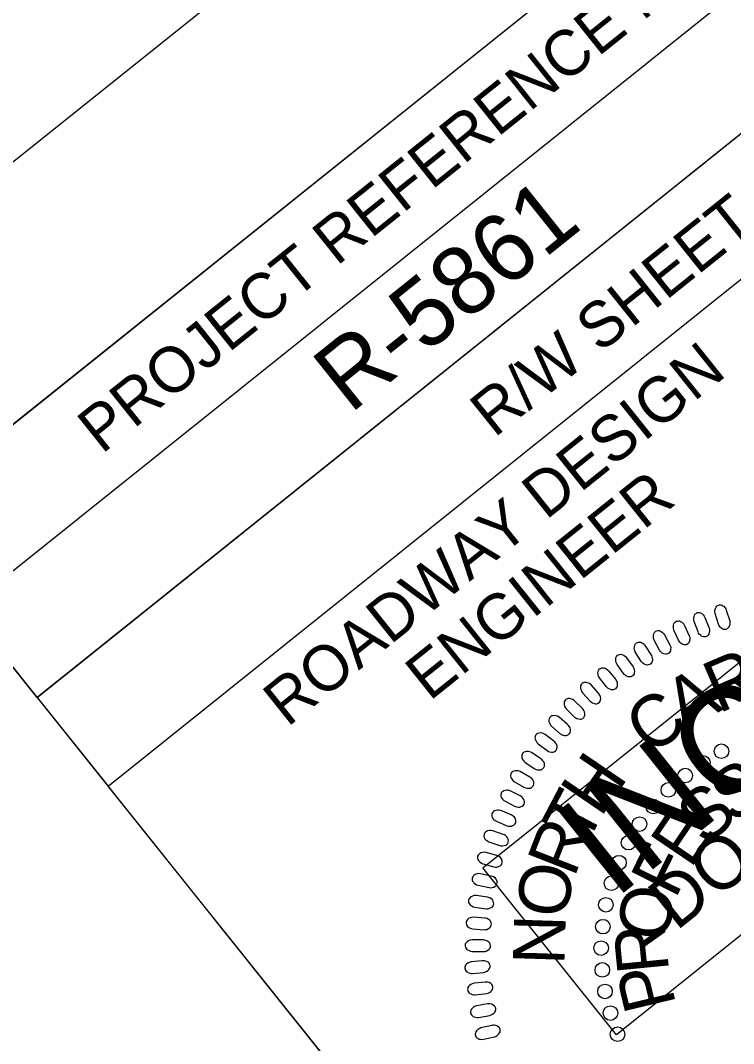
# Model space of a CAD drawing. Extents: x 473546 to 475544, y 505920 to 507827.
# Drawn here: x 474718.5 to 474796.9, y 507616 to 507728.4 of the extents above; entities that cross this region are included whole.
import ezdxf

# ---------------------------------------------------------------- set-up
doc = ezdxf.new("R2010")
doc.units = 0
for name, color, linetype in [('Sheet Clip Boundary CELL', 7, 'Continuous'), ('Sheet Data Field CELL', 7, 'Continuous'), ('Sheet Plan CELL', 7, 'Continuous'), ('Sheet Plot Border Outside CELL', 7, 'Continuous'), ('Sheet Profile Grid Minor CELL', 7, 'Continuous'), ('Sheet Sticker Incomplete CELL', 7, 'Continuous')]:
    doc.layers.add(name, color=color, linetype=linetype)

msp = doc.modelspace()

# ---------------------------------------------------------------- linework, layer by layer
at = {"layer": 'Sheet Clip Boundary CELL'}
msp.add_lwpolyline([(474813.14, 507538.12), (474704.64, 507673.67), (473746.99, 506907.14), (474401.7, 506086.25), (475384.17, 506871.79), (475333.84, 506934.75), (475466.73, 507041), (474969.31, 507663.12)], close=True, dxfattribs=at)
at = {"layer": 'Sheet Plan CELL'}
for p, q in [((474712.51, 507663.81), (474868.71, 507788.81)), ((474720.35, 507654.03), (474876.52, 507779.05)), ((474720.35, 507654.03), (474876.52, 507779.05)), ((474720.35, 507654.03), (474728.16, 507644.28))]:
    msp.add_line(p, q, dxfattribs=at)
for points in [[(474860.89, 507798.63), (473689.75, 506861.33), (474345.84, 506041.55), (475516.97, 506978.83)], [(474704.68, 507673.62), (474860.89, 507798.63), (474876.52, 507779.05), (474720.35, 507654.03)], [(474728.16, 507644.28), (474806.27, 507706.8), (474876.57, 507618.96), (474798.45, 507556.47)]]:
    msp.add_lwpolyline(points, close=True, dxfattribs=at)
at = {"layer": 'Sheet Plot Border Outside CELL'}
msp.add_lwpolyline([(474229.92, 505919.94), (475544.31, 506971.88), (474860.1, 507826.79), (473545.71, 506774.86)], close=True, dxfattribs=at)
at = {"layer": 'Sheet Profile Grid Minor CELL'}
for points in [[(474795.23, 507662.07), (474794.87, 507663.25), (474794.84, 507663.47), (474794.85, 507663.62), (474794.91, 507663.81), (474794.97, 507663.94), (474795.06, 507664.05), (474795.14, 507664.12), (474795.24, 507664.17), (474795.36, 507664.19), (474795.48, 507664.19), (474795.6, 507664.17), (474795.73, 507664.1), (474795.81, 507664.04), (474795.92, 507663.92), (474796.03, 507663.77), (474796.1, 507663.62), (474796.47, 507662.42), (474796.5, 507662.25), (474796.5, 507662.11), (474796.46, 507661.93), (474796.39, 507661.76), (474796.32, 507661.66), (474796.19, 507661.55), (474796.05, 507661.49), (474795.9, 507661.49), (474795.78, 507661.5), (474795.63, 507661.56), (474795.47, 507661.69), (474795.35, 507661.84), (474795.29, 507661.95)], [(474792.99, 507661.22), (474792.56, 507662.37), (474792.52, 507662.59), (474792.52, 507662.74), (474792.56, 507662.93), (474792.61, 507663.07), (474792.69, 507663.19), (474792.77, 507663.26), (474792.87, 507663.32), (474792.98, 507663.34), (474793.11, 507663.35), (474793.23, 507663.33), (474793.36, 507663.28), (474793.44, 507663.22), (474793.56, 507663.11), (474793.68, 507662.96), (474793.75, 507662.82), (474794.2, 507661.65), (474794.24, 507661.48), (474794.25, 507661.33), (474794.22, 507661.15), (474794.17, 507660.98), (474794.1, 507660.87), (474793.98, 507660.76), (474793.85, 507660.69), (474793.69, 507660.67), (474793.58, 507660.68), (474793.42, 507660.73), (474793.25, 507660.85), (474793.12, 507660.99), (474793.05, 507661.1)], [(474790.85, 507660.3), (474790.34, 507661.42), (474790.29, 507661.63), (474790.28, 507661.78), (474790.31, 507661.98), (474790.35, 507662.12), (474790.42, 507662.24), (474790.5, 507662.32), (474790.59, 507662.39), (474790.7, 507662.41), (474790.83, 507662.44), (474790.95, 507662.42), (474791.08, 507662.38), (474791.17, 507662.33), (474791.29, 507662.22), (474791.42, 507662.08), (474791.51, 507661.94), (474792.03, 507660.8), (474792.08, 507660.64), (474792.09, 507660.49), (474792.08, 507660.31), (474792.03, 507660.14), (474791.98, 507660.02), (474791.86, 507659.9), (474791.73, 507659.82), (474791.58, 507659.8), (474791.46, 507659.8), (474791.31, 507659.84), (474791.13, 507659.95), (474790.99, 507660.08), (474790.91, 507660.19)], [(474788.75, 507659.23), (474788.18, 507660.31), (474788.11, 507660.53), (474788.09, 507660.67), (474788.11, 507660.88), (474788.14, 507661.02), (474788.2, 507661.14), (474788.28, 507661.23), (474788.37, 507661.3), (474788.48, 507661.33), (474788.6, 507661.36), (474788.72, 507661.36), (474788.86, 507661.32), (474788.95, 507661.27), (474789.08, 507661.17), (474789.21, 507661.04), (474789.31, 507660.91), (474789.9, 507659.8), (474789.96, 507659.64), (474789.99, 507659.5), (474789.98, 507659.32), (474789.95, 507659.14), (474789.9, 507659.02), (474789.79, 507658.9), (474789.66, 507658.81), (474789.51, 507658.78), (474789.4, 507658.77), (474789.24, 507658.8), (474789.05, 507658.89), (474788.91, 507659.02), (474788.82, 507659.12)], [(474786.74, 507657.99), (474786.1, 507659.04), (474786.02, 507659.25), (474785.99, 507659.39), (474786, 507659.59), (474786.03, 507659.74), (474786.08, 507659.87), (474786.15, 507659.95), (474786.23, 507660.03), (474786.34, 507660.07), (474786.46, 507660.11), (474786.58, 507660.11), (474786.72, 507660.08), (474786.81, 507660.04), (474786.95, 507659.95), (474787.09, 507659.83), (474787.19, 507659.71), (474787.86, 507658.64), (474787.93, 507658.48), (474787.96, 507658.34), (474787.97, 507658.16), (474787.94, 507657.98), (474787.9, 507657.86), (474787.8, 507657.73), (474787.68, 507657.63), (474787.53, 507657.59), (474787.42, 507657.57), (474787.26, 507657.59), (474787.07, 507657.68), (474786.92, 507657.79), (474786.82, 507657.89)], [(474784.79, 507656.65), (474784.09, 507657.66), (474783.99, 507657.86), (474783.95, 507658), (474783.95, 507658.21), (474783.96, 507658.35), (474784.01, 507658.48), (474784.07, 507658.57), (474784.15, 507658.65), (474784.26, 507658.7), (474784.37, 507658.75), (474784.49, 507658.76), (474784.63, 507658.74), (474784.73, 507658.7), (474784.87, 507658.62), (474785.02, 507658.51), (474785.13, 507658.39), (474785.86, 507657.37), (474785.94, 507657.21), (474785.98, 507657.07), (474786, 507656.89), (474785.99, 507656.71), (474785.96, 507656.59), (474785.86, 507656.45), (474785.75, 507656.35), (474785.6, 507656.3), (474785.49, 507656.28), (474785.33, 507656.29), (474785.13, 507656.36), (474784.98, 507656.47), (474784.88, 507656.56)], [(474782.93, 507655.2), (474782.17, 507656.16), (474782.06, 507656.35), (474782.01, 507656.49), (474781.99, 507656.7), (474782, 507656.84), (474782.04, 507656.97), (474782.09, 507657.07), (474782.17, 507657.16), (474782.27, 507657.21), (474782.38, 507657.26), (474782.5, 507657.28), (474782.65, 507657.27), (474782.74, 507657.24), (474782.89, 507657.17), (474783.05, 507657.07), (474783.16, 507656.96), (474783.95, 507655.98), (474784.04, 507655.83), (474784.1, 507655.7), (474784.12, 507655.51), (474784.12, 507655.34), (474784.1, 507655.21), (474784.01, 507655.07), (474783.91, 507654.96), (474783.77, 507654.9), (474783.65, 507654.87), (474783.49, 507654.87), (474783.29, 507654.93), (474783.13, 507655.02), (474783.02, 507655.11)], [(474782.07, 507654.49), (474781.24, 507655.4), (474781.07, 507655.54), (474780.93, 507655.61), (474780.74, 507655.66), (474780.59, 507655.67), (474780.45, 507655.66), (474780.35, 507655.62), (474780.25, 507655.56), (474780.18, 507655.47), (474780.12, 507655.36), (474780.08, 507655.25), (474780.07, 507655.1), (474780.08, 507655.01), (474780.13, 507654.85), (474780.2, 507654.68), (474780.3, 507654.54), (474781.14, 507653.61), (474781.27, 507653.5), (474781.39, 507653.42), (474781.57, 507653.37), (474781.74, 507653.34), (474781.87, 507653.34), (474782.03, 507653.41), (474782.15, 507653.49), (474782.23, 507653.62), (474782.28, 507653.73), (474782.3, 507653.89), (474782.28, 507654.09), (474782.21, 507654.27), (474782.14, 507654.39)], [(474780.29, 507652.81), (474779.41, 507653.67), (474779.23, 507653.79), (474779.09, 507653.85), (474778.89, 507653.89), (474778.74, 507653.9), (474778.61, 507653.87), (474778.51, 507653.83), (474778.41, 507653.76), (474778.35, 507653.66), (474778.29, 507653.56), (474778.26, 507653.44), (474778.26, 507653.3), (474778.27, 507653.2), (474778.33, 507653.05), (474778.42, 507652.88), (474778.52, 507652.75), (474779.42, 507651.87), (474779.55, 507651.77), (474779.68, 507651.7), (474779.86, 507651.66), (474780.04, 507651.64), (474780.16, 507651.65), (474780.32, 507651.72), (474780.44, 507651.82), (474780.51, 507651.95), (474780.55, 507652.06), (474780.56, 507652.22), (474780.53, 507652.43), (474780.44, 507652.6), (474780.37, 507652.71)], [(474778.66, 507651.04), (474777.73, 507651.84), (474777.54, 507651.95), (474777.4, 507652), (474777.2, 507652.03), (474777.05, 507652.02), (474776.92, 507651.99), (474776.82, 507651.94), (474776.73, 507651.86), (474776.67, 507651.77), (474776.62, 507651.66), (474776.59, 507651.54), (474776.6, 507651.39), (474776.62, 507651.3), (474776.69, 507651.15), (474776.79, 507650.99), (474776.9, 507650.86), (474777.85, 507650.04), (474777.99, 507649.95), (474778.13, 507649.89), (474778.31, 507649.86), (474778.48, 507649.85), (474778.61, 507649.87), (474778.76, 507649.95), (474778.87, 507650.05), (474778.94, 507650.19), (474778.97, 507650.31), (474778.97, 507650.47), (474778.92, 507650.67), (474778.83, 507650.84), (474778.75, 507650.94)], [(474777.16, 507649.23), (474776.18, 507649.97), (474775.98, 507650.07), (474775.83, 507650.11), (474775.63, 507650.12), (474775.49, 507650.11), (474775.35, 507650.07), (474775.26, 507650.01), (474775.18, 507649.93), (474775.12, 507649.83), (474775.08, 507649.72), (474775.06, 507649.6), (474775.08, 507649.45), (474775.11, 507649.36), (474775.19, 507649.21), (474775.29, 507649.06), (474775.41, 507648.94), (474776.41, 507648.18), (474776.56, 507648.1), (474776.69, 507648.05), (474776.88, 507648.03), (474777.05, 507648.03), (474777.18, 507648.06), (474777.32, 507648.15), (474777.42, 507648.26), (474777.48, 507648.4), (474777.51, 507648.52), (474777.5, 507648.68), (474777.44, 507648.88), (474777.34, 507649.04), (474777.25, 507649.14)], [(474775.72, 507647.29), (474774.7, 507647.96), (474774.49, 507648.05), (474774.35, 507648.08), (474774.14, 507648.08), (474774, 507648.06), (474773.87, 507648.01), (474773.78, 507647.95), (474773.7, 507647.86), (474773.66, 507647.76), (474773.62, 507647.64), (474773.61, 507647.52), (474773.63, 507647.38), (474773.67, 507647.29), (474773.76, 507647.15), (474773.87, 507647), (474773.99, 507646.89), (474775.04, 507646.2), (474775.19, 507646.12), (474775.33, 507646.08), (474775.52, 507646.07), (474775.7, 507646.09), (474775.82, 507646.12), (474775.95, 507646.22), (474776.05, 507646.34), (474776.1, 507646.48), (474776.12, 507646.6), (474776.1, 507646.76), (474776.03, 507646.95), (474775.91, 507647.11), (474775.82, 507647.2)], [(474774.51, 507645.27), (474773.45, 507645.88), (474773.24, 507645.96), (474773.09, 507645.98), (474772.89, 507645.97), (474772.75, 507645.94), (474772.62, 507645.88), (474772.53, 507645.81), (474772.46, 507645.72), (474772.42, 507645.62), (474772.39, 507645.5), (474772.39, 507645.38), (474772.42, 507645.24), (474772.46, 507645.14), (474772.56, 507645.01), (474772.69, 507644.87), (474772.81, 507644.77), (474773.9, 507644.14), (474774.06, 507644.08), (474774.2, 507644.05), (474774.39, 507644.05), (474774.56, 507644.07), (474774.68, 507644.12), (474774.81, 507644.23), (474774.9, 507644.35), (474774.94, 507644.5), (474774.95, 507644.61), (474774.93, 507644.77), (474774.84, 507644.96), (474774.72, 507645.11), (474774.62, 507645.2)], [(474773.44, 507643.22), (474772.34, 507643.76), (474772.13, 507643.83), (474771.98, 507643.84), (474771.78, 507643.82), (474771.64, 507643.78), (474771.52, 507643.71), (474771.43, 507643.63), (474771.37, 507643.54), (474771.34, 507643.43), (474771.31, 507643.31), (474771.32, 507643.19), (474771.36, 507643.05), (474771.41, 507642.97), (474771.51, 507642.84), (474771.65, 507642.71), (474771.78, 507642.62), (474772.9, 507642.06), (474773.07, 507642), (474773.21, 507641.98), (474773.39, 507641.99), (474773.57, 507642.03), (474773.68, 507642.08), (474773.81, 507642.2), (474773.89, 507642.32), (474773.92, 507642.47), (474773.92, 507642.59), (474773.89, 507642.75), (474773.79, 507642.93), (474773.66, 507643.07), (474773.55, 507643.15)], [(474772.45, 507641.13), (474771.32, 507641.6), (474771.1, 507641.65), (474770.95, 507641.65), (474770.75, 507641.62), (474770.61, 507641.57), (474770.5, 507641.5), (474770.42, 507641.41), (474770.36, 507641.32), (474770.33, 507641.21), (474770.31, 507641.08), (474770.33, 507640.97), (474770.38, 507640.83), (474770.43, 507640.74), (474770.55, 507640.62), (474770.69, 507640.5), (474770.83, 507640.42), (474771.99, 507639.93), (474772.15, 507639.89), (474772.3, 507639.87), (474772.48, 507639.9), (474772.65, 507639.95), (474772.76, 507640), (474772.88, 507640.13), (474772.95, 507640.26), (474772.97, 507640.41), (474772.97, 507640.53), (474772.92, 507640.68), (474772.81, 507640.86), (474772.67, 507640.99), (474772.56, 507641.07)], [(474771.59, 507638.98), (474770.43, 507639.37), (474770.21, 507639.41), (474770.06, 507639.41), (474769.86, 507639.36), (474769.73, 507639.3), (474769.62, 507639.22), (474769.54, 507639.13), (474769.49, 507639.03), (474769.47, 507638.92), (474769.46, 507638.8), (474769.48, 507638.68), (474769.54, 507638.55), (474769.6, 507638.47), (474769.72, 507638.35), (474769.87, 507638.24), (474770.01, 507638.17), (474771.2, 507637.75), (474771.37, 507637.72), (474771.51, 507637.71), (474771.69, 507637.75), (474771.86, 507637.81), (474771.97, 507637.87), (474772.08, 507638), (474772.14, 507638.14), (474772.16, 507638.29), (474772.14, 507638.41), (474772.09, 507638.56), (474771.97, 507638.73), (474771.82, 507638.85), (474771.71, 507638.92)], [(474770.87, 507636.67), (474769.69, 507636.99), (474769.47, 507637.02), (474769.32, 507637), (474769.13, 507636.94), (474769, 507636.87), (474768.89, 507636.79), (474768.82, 507636.7), (474768.77, 507636.59), (474768.76, 507636.48), (474768.76, 507636.36), (474768.79, 507636.24), (474768.86, 507636.11), (474768.92, 507636.03), (474769.05, 507635.93), (474769.2, 507635.82), (474769.35, 507635.76), (474770.56, 507635.42), (474770.73, 507635.4), (474770.88, 507635.4), (474771.06, 507635.45), (474771.22, 507635.52), (474771.32, 507635.59), (474771.42, 507635.73), (474771.48, 507635.87), (474771.48, 507636.02), (474771.46, 507636.14), (474771.4, 507636.28), (474771.27, 507636.44), (474771.11, 507636.56), (474770.99, 507636.62)], [(474770.27, 507634.41), (474769.07, 507634.66), (474768.85, 507634.67), (474768.7, 507634.64), (474768.51, 507634.57), (474768.39, 507634.5), (474768.29, 507634.4), (474768.23, 507634.31), (474768.18, 507634.2), (474768.18, 507634.09), (474768.18, 507633.97), (474768.22, 507633.85), (474768.3, 507633.73), (474768.36, 507633.65), (474768.5, 507633.56), (474768.66, 507633.46), (474768.81, 507633.41), (474770.04, 507633.14), (474770.21, 507633.13), (474770.36, 507633.15), (474770.53, 507633.2), (474770.69, 507633.28), (474770.79, 507633.36), (474770.88, 507633.5), (474770.93, 507633.65), (474770.92, 507633.8), (474770.89, 507633.91), (474770.82, 507634.06), (474770.68, 507634.21), (474770.52, 507634.31), (474770.4, 507634.37)], [(474769.84, 507632.09), (474768.62, 507632.26), (474768.4, 507632.26), (474768.26, 507632.23), (474768.07, 507632.14), (474767.95, 507632.06), (474767.86, 507631.96), (474767.8, 507631.86), (474767.77, 507631.75), (474767.77, 507631.64), (474767.78, 507631.52), (474767.83, 507631.41), (474767.91, 507631.29), (474767.98, 507631.22), (474768.12, 507631.13), (474768.29, 507631.04), (474768.44, 507631), (474769.69, 507630.81), (474769.86, 507630.81), (474770, 507630.84), (474770.17, 507630.9), (474770.33, 507630.99), (474770.42, 507631.08), (474770.5, 507631.23), (474770.54, 507631.37), (474770.52, 507631.52), (474770.49, 507631.64), (474770.41, 507631.78), (474770.26, 507631.92), (474770.09, 507632.01), (474769.97, 507632.06)], [(474769.55, 507629.8), (474768.32, 507629.89), (474768.1, 507629.87), (474767.96, 507629.83), (474767.78, 507629.73), (474767.66, 507629.65), (474767.58, 507629.54), (474767.53, 507629.44), (474767.5, 507629.33), (474767.51, 507629.22), (474767.53, 507629.09), (474767.58, 507628.99), (474767.67, 507628.87), (474767.75, 507628.81), (474767.89, 507628.73), (474768.06, 507628.65), (474768.22, 507628.62), (474769.47, 507628.51), (474769.64, 507628.52), (474769.79, 507628.55), (474769.95, 507628.63), (474770.1, 507628.73), (474770.19, 507628.82), (474770.26, 507628.97), (474770.29, 507629.12), (474770.26, 507629.27), (474770.22, 507629.38), (474770.13, 507629.52), (474769.97, 507629.65), (474769.8, 507629.73), (474769.67, 507629.77)], [(474769.4, 507627.39), (474768.18, 507627.41), (474767.96, 507627.38), (474767.82, 507627.33), (474767.64, 507627.22), (474767.53, 507627.12), (474767.45, 507627.01), (474767.41, 507626.91), (474767.39, 507626.8), (474767.41, 507626.69), (474767.44, 507626.57), (474767.49, 507626.46), (474767.59, 507626.35), (474767.67, 507626.29), (474767.82, 507626.22), (474768, 507626.16), (474768.16, 507626.13), (474769.41, 507626.11), (474769.58, 507626.13), (474769.72, 507626.17), (474769.88, 507626.26), (474770.02, 507626.37), (474770.11, 507626.46), (474770.17, 507626.62), (474770.19, 507626.77), (474770.15, 507626.92), (474770.11, 507627.02), (474770.01, 507627.15), (474769.84, 507627.27), (474769.66, 507627.34), (474769.53, 507627.38)], [(474769.28, 507625.11), (474768.06, 507624.99), (474767.84, 507624.93), (474767.71, 507624.86), (474767.55, 507624.73), (474767.45, 507624.63), (474767.38, 507624.51), (474767.35, 507624.4), (474767.35, 507624.28), (474767.38, 507624.17), (474767.42, 507624.06), (474767.49, 507623.96), (474767.6, 507623.87), (474767.68, 507623.81), (474767.84, 507623.76), (474768.03, 507623.72), (474768.19, 507623.72), (474769.44, 507623.83), (474769.6, 507623.87), (474769.74, 507623.93), (474769.89, 507624.04), (474770.01, 507624.16), (474770.08, 507624.27), (474770.13, 507624.43), (474770.13, 507624.58), (474770.08, 507624.73), (474770.02, 507624.83), (474769.91, 507624.94), (474769.73, 507625.04), (474769.54, 507625.09), (474769.41, 507625.11)], [(474769.59, 507622.77), (474768.37, 507622.64), (474768.16, 507622.58), (474768.03, 507622.51), (474767.87, 507622.38), (474767.77, 507622.27), (474767.7, 507622.15), (474767.68, 507622.04), (474767.67, 507621.93), (474767.7, 507621.82), (474767.74, 507621.71), (474767.81, 507621.61), (474767.92, 507621.52), (474768.01, 507621.46), (474768.17, 507621.41), (474768.35, 507621.37), (474768.51, 507621.37), (474769.76, 507621.5), (474769.93, 507621.54), (474770.06, 507621.6), (474770.21, 507621.71), (474770.34, 507621.83), (474770.41, 507621.94), (474770.45, 507622.1), (474770.45, 507622.25), (474770.4, 507622.39), (474770.34, 507622.49), (474770.22, 507622.61), (474770.04, 507622.71), (474769.86, 507622.76), (474769.72, 507622.77)], [(474769.86, 507620.36), (474768.65, 507620.15), (474768.44, 507620.07), (474768.31, 507620), (474768.16, 507619.86), (474768.07, 507619.74), (474768.01, 507619.62), (474767.99, 507619.51), (474767.99, 507619.4), (474768.03, 507619.29), (474768.08, 507619.18), (474768.15, 507619.08), (474768.27, 507619), (474768.36, 507618.95), (474768.52, 507618.91), (474768.7, 507618.88), (474768.87, 507618.89), (474770.1, 507619.1), (474770.27, 507619.15), (474770.4, 507619.22), (474770.54, 507619.33), (474770.66, 507619.47), (474770.72, 507619.58), (474770.75, 507619.74), (474770.75, 507619.89), (474770.68, 507620.03), (474770.61, 507620.13), (474770.49, 507620.23), (474770.31, 507620.32), (474770.12, 507620.36), (474769.99, 507620.37)], [(474770.32, 507618.01), (474769.12, 507617.72), (474768.92, 507617.64), (474768.8, 507617.55), (474768.66, 507617.4), (474768.57, 507617.28), (474768.52, 507617.16), (474768.51, 507617.04), (474768.51, 507616.93), (474768.56, 507616.83), (474768.62, 507616.72), (474768.7, 507616.63), (474768.82, 507616.55), (474768.91, 507616.51), (474769.07, 507616.48), (474769.26, 507616.46), (474769.42, 507616.48), (474770.65, 507616.76), (474770.8, 507616.83), (474770.93, 507616.9), (474771.06, 507617.03), (474771.17, 507617.17), (474771.23, 507617.28), (474771.25, 507617.45), (474771.24, 507617.6), (474771.16, 507617.73), (474771.09, 507617.82), (474770.96, 507617.92), (474770.77, 507618), (474770.58, 507618.02), (474770.45, 507618.02)]]:
    msp.add_lwpolyline(points, close=True, dxfattribs=at)
for centre in [(474795.56, 507648.12), (474793.52, 507646.85), (474791.58, 507645.45), (474789.73, 507643.87), (474788.08, 507642.04), (474786.57, 507640.11), (474785.35, 507638.07), (474784.31, 507635.88), (474783.47, 507633.62), (474782.86, 507631.25), (474782.54, 507628.85), (474782.34, 507626.49), (474782.47, 507624.1), (474782.77, 507621.74), (474783.36, 507619.35), (474784.15, 507617.03)]:
    msp.add_circle(centre, 0.801, dxfattribs=at)
at = {"layer": 'Sheet Sticker Incomplete CELL'}
msp.add_lwpolyline([(474784.03, 507616.96), (474769.35, 507635.3), (474884.12, 507727.16), (474898.8, 507708.81)], close=True, dxfattribs=at)

# ---------------------------------------------------------------- texts
at = {"layer": 'Sheet Data Field CELL'}
msp.add_text('R-5861', height=7.5, rotation=38.6712, dxfattribs=at).set_placement((474754.75, 507685.1))
at = {"layer": 'Sheet Plan CELL'}
for s, height, p in [('PROJECT REFERENCE NO.', 5.0001, (474727.46, 507680.68)), ('R/W SHEET NO.', 5.0001, (474770.6, 507682.48)), ('ROADWAY DESIGN', 5.0001, (474747.85, 507650.69)), ('ENGINEER', 5, (474763.48, 507653.55))]:
    msp.add_text(s, height=height, rotation=38.6712, dxfattribs=at).set_placement(p)
at = {"layer": 'Sheet Profile Grid Minor CELL'}
for s, rotation, p in [('R', 23.2802, (474795.24, 507652.23)), ('A', 29.7695, (474791.46, 507650.22)), ('C', 36.2589, (474787.76, 507647.53)), ('H', 55.727, (474782.29, 507640.74)), ('S', 32.0205, (474796.69, 507640.08)), ('T', 62.2163, (474780.69, 507637.66)), ('S', 39.9603, (474793.74, 507637.59)), ('E', 55.8398, (474792.18, 507635.11)), ('R', 68.7057, (474779.38, 507634.14)), ('F', 63.7796, (474790.49, 507631.79)), ('O', 81.6844, (474778.56, 507629.61)), ('O', 79.6592, (474789.56, 507627.03)), ('N', 88.1738, (474778.29, 507624.59)), ('R', 95.5388, (474789.82, 507623.97)), ('P', 103.4786, (474790.6, 507620.3))]:
    msp.add_text(s, height=5.67, rotation=rotation, dxfattribs=at).set_placement(p)
at = {"layer": 'Sheet Sticker Incomplete CELL'}
for s, height, p in [('INCOMPLETE PLANS', 11.52, (474783.71, 507631.68)), ('DO NOT USE FOR R/W ACQUISITION', 5.76, (474790.59, 507628.29))]:
    msp.add_text(s, height=height, rotation=38.6712, dxfattribs=at).set_placement(p)

doc.saveas('drawing.dxf')
